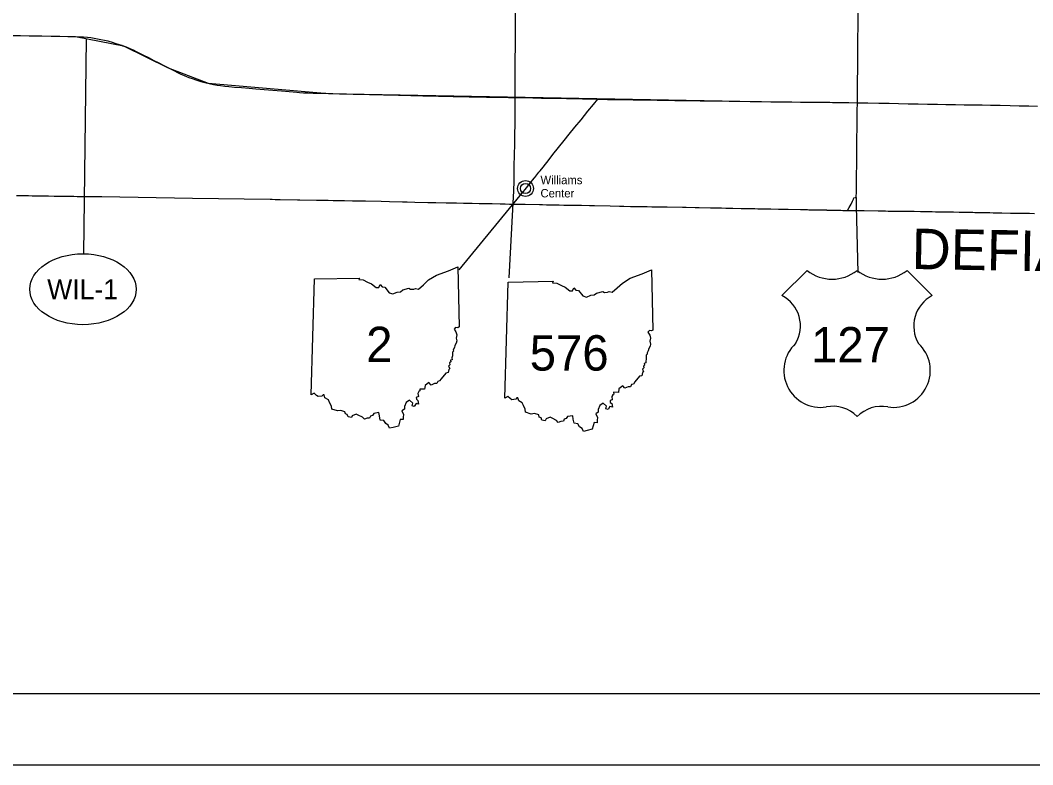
# Model space of a CAD drawing. Extents: x -66 to 795, y 0 to 440.
# Drawn here: x 240.8 to 383.6, y 0 to 105 of the extents above; entities that cross this region are included whole.
import ezdxf

# ---------------------------------------------------------------- set-up
doc = ezdxf.new("R2010")
doc.units = 0
for name, color, linetype in [('DV_X_Corp_Line', 7, 'Continuous'), ('GM_X_Adjacent_County_Text', 7, 'Continuous'), ('GM_X_County', 7, 'Continuous'), ('GM_X_State_Route', 7, 'Continuous'), ('GM_X_US_Route', 7, 'Continuous'), ('PV_P_Text', 7, 'Continuous'), ('RD_P_Fence', 7, 'Continuous'), ('SH_Border', 7, 'Continuous'), ('SH_Cut_Line', 7, 'Continuous'), ('SH_Data', 7, 'Continuous')]:
    doc.layers.add(name, color=color, linetype=linetype)

msp = doc.modelspace()

# ---------------------------------------------------------------- linework, layer by layer
at = {"layer": 'DV_X_Corp_Line'}
for radius in [1.12, 0.71]:
    msp.add_circle((312.08, 81.27), radius, dxfattribs=at)
at = {"layer": 'GM_X_County'}
msp.add_lwpolyline([(240.33, 80.3), (241.04, 80.29), (242.03, 80.26), (242.53, 80.25), (243.51, 80.24), (244.82, 80.22), (245.64, 80.21), (246.9, 80.19), (247.4, 80.19), (247.99, 80.18), (248.41, 80.17), (248.86, 80.16), (249.37, 80.16), (252.25, 80.12), (252.27, 80.12), (252.3, 80.12), (252.35, 80.12), (265.13, 79.9), (276.07, 79.77), (276.35, 79.75), (276.78, 79.74), (277.51, 79.73), (279.93, 79.69), (280.29, 79.68), (282.64, 79.64), (284.24, 79.61), (284.99, 79.59), (286.55, 79.57), (287.69, 79.55), (288.6, 79.53), (289.52, 79.51), (291.73, 79.46), (292.92, 79.44), (294.74, 79.39), (295.1, 79.39), (295.24, 79.38), (295.35, 79.38), (295.41, 79.38), (296.49, 79.35), (298.32, 79.31), (299.43, 79.28), (300.88, 79.25), (302.36, 79.23), (303.35, 79.21), (304.55, 79.18), (305.56, 79.17), (306.83, 79.14), (307.37, 79.13), (308.51, 79.11), (309.22, 79.1), (309.85, 79.08), (310.35, 79.07), (310.84, 79.06), (311.28, 79.05), (311.78, 79.05), (312.02, 79.05), (314.07, 79), (314.46, 79), (315.05, 78.98), (316.85, 78.95), (317.48, 78.94), (319.31, 78.91), (319.96, 78.9), (321.13, 78.87), (321.8, 78.86), (324.03, 78.81), (325.36, 78.78), (325.93, 78.77), (326.91, 78.75), (327.66, 78.74), (328.3, 78.73), (329.24, 78.71), (329.89, 78.7), (331.41, 78.68), (332.04, 78.67), (334.23, 78.63), (334.73, 78.63), (336.02, 78.6), (336.58, 78.59), (338.15, 78.56), (338.88, 78.54), (339.72, 78.53), (340.32, 78.51), (340.4, 78.51), (340.58, 78.51), (341.3, 78.49), (342.48, 78.47), (343.11, 78.45), (343.73, 78.44), (343.99, 78.44), (344.44, 78.43), (344.86, 78.42), (345.4, 78.41), (345.76, 78.4), (346.16, 78.39), (346.46, 78.38), (346.69, 78.38), (347.76, 78.36), (348.23, 78.35), (348.47, 78.34), (349.12, 78.33), (350.86, 78.29), (351.25, 78.29), (351.4, 78.29), (351.64, 78.29), (351.83, 78.29), (352.04, 78.28), (352.33, 78.28), (352.56, 78.27), (352.87, 78.26), (353.39, 78.25), (353.81, 78.24), (354.2, 78.24), (354.51, 78.24), (354.58, 78.23), (354.86, 78.23), (354.92, 78.23), (355.11, 78.22), (355.34, 78.21), (355.59, 78.21), (355.97, 78.2), (356.27, 78.19), (356.56, 78.19), (356.85, 78.18), (357.09, 78.18), (357.47, 78.17), (357.91, 78.17), (358.27, 78.16), (358.58, 78.16), (358.72, 78.16), (359.13, 78.16), (359.82, 78.15), (361.82, 78.11), (362.51, 78.1), (362.86, 78.1), (363.21, 78.09), (363.51, 78.09), (363.89, 78.08), (364.6, 78.07), (365.53, 78.07), (366.14, 78.05), (366.9, 78.05), (367.79, 78.04), (368.48, 78.03), (369.42, 78.01), (369.88, 78), (369.99, 78), (370.71, 77.99), (371.11, 77.98), (371.44, 77.98), (372.41, 77.96), (373.22, 77.95), (373.91, 77.93), (374.91, 77.91), (375.15, 77.91), (375.44, 77.9), (375.81, 77.9), (376.3, 77.89), (376.67, 77.88), (377.15, 77.87), (377.56, 77.86), (378.02, 77.85), (378.46, 77.85), (379.26, 77.84), (380.48, 77.81), (381.17, 77.8), (381.8, 77.79), (382.4, 77.78), (383.13, 77.77), (383.85, 77.76)], dxfattribs=at)
at = {"layer": 'GM_X_State_Route'}
for points in [[(309.8, 68.69), (310.45, 80.94), (310.47, 82.32), (310.48, 82.56), (310.48, 82.85), (310.5, 83.32), (310.5, 83.77), (310.51, 84.41), (310.54, 86.01), (310.57, 87.51), (310.59, 88.93), (310.61, 90.28), (310.62, 91.57), (310.62, 92.89), (310.64, 94.09), (310.64, 95.83), (310.65, 97.86), (310.65, 99.54), (310.67, 101.22), (310.67, 102.96), (310.68, 104.82), (310.69, 106.4)], [(302.71, 69.79), (311.33, 80.26), (312.02, 81.13), (312.04, 81.15), (312.22, 81.37), (312.69, 81.96), (313.3, 82.72), (313.33, 82.76), (313.38, 82.82), (313.96, 83.55), (314.13, 83.75), (314.56, 84.29), (315.4, 85.36), (316.09, 86.24), (316.38, 86.6), (316.72, 87.04), (317.54, 88.03), (318.26, 88.92), (319.06, 89.9), (319.93, 90.97), (320.89, 92.16), (321.68, 93.12), (322.28, 93.87)], [(358.72, 80), (358.71, 79.48), (358.7, 78.76), (358.92, 69.44)]]:
    msp.add_lwpolyline(points, dxfattribs=at)
at = {"layer": 'GM_X_US_Route'}
for points in [[(358.96, 102.97), (358.97, 103.54), (358.99, 105.1), (358.99, 106.44), (359, 107.65), (359.01, 107.92)], [(239.46, 102.86), (240.87, 102.83), (242.28, 102.81), (243.87, 102.78), (245.21, 102.76), (246.42, 102.74), (247.55, 102.71), (248.59, 102.7), (249.17, 102.67), (249.79, 102.64), (250.34, 102.6), (250.78, 102.54), (251.27, 102.47), (251.76, 102.39), (252.23, 102.29), (252.75, 102.18), (253.19, 102.08), (253.79, 101.92), (254.34, 101.74), (254.81, 101.58), (255.16, 101.46), (255.32, 101.41), (255.78, 101.24), (256.28, 101.03), (256.76, 100.81), (257.29, 100.55), (258.13, 100.13), (258.93, 99.72), (259.69, 99.34), (260.37, 98.99), (261.11, 98.6), (261.77, 98.27), (262.49, 97.89), (263.01, 97.63), (263.48, 97.41), (263.95, 97.2), (264.39, 97.03), (264.76, 96.89), (265.08, 96.78), (265.76, 96.55), (266.32, 96.37), (266.86, 96.23), (267.47, 96.08), (268.08, 95.94), (268.6, 95.84), (269.06, 95.78), (269.71, 95.69), (270.28, 95.65), (271.06, 95.57), (272.06, 95.49), (273.14, 95.4), (274.08, 95.33), (275.22, 95.22), (276.48, 95.13), (277.7, 95.03), (278.78, 94.94), (279.85, 94.85), (280.24, 94.82), (280.78, 94.78), (281.46, 94.74), (282.16, 94.72), (283.1, 94.71), (283.94, 94.69), (284.9, 94.66), (285.87, 94.64), (286.84, 94.62), (287.8, 94.59), (288.91, 94.58), (290.09, 94.54), (291.2, 94.52), (292.05, 94.5), (293.09, 94.47), (294.16, 94.45), (295.12, 94.42), (295.39, 94.41), (295.94, 94.4), (296.58, 94.38), (297.61, 94.36), (298.78, 94.34), (299.81, 94.31), (300.79, 94.28), (301.88, 94.26), (303, 94.24), (304.12, 94.21), (305.39, 94.19), (306.57, 94.17), (307.7, 94.15), (308.71, 94.13), (309.71, 94.11), (310.64, 94.09)], [(358.95, 101.77), (358.95, 102.53), (358.96, 102.87), (358.96, 102.97)], [(358.88, 93.36), (358.89, 94.87), (358.91, 96.51), (358.92, 98.05), (358.94, 99.65), (358.95, 101.12), (358.95, 101.68), (358.95, 101.77)], [(310.64, 94.09), (311.83, 94.08), (313.1, 94.05), (314.34, 94.03), (315.51, 94.01), (316.68, 93.99), (317.85, 93.97), (318.98, 93.94), (320.1, 93.93), (321.21, 93.9), (321.23, 93.9)], [(321.23, 93.9), (322.28, 93.87)], [(322.28, 93.87), (323.11, 93.85)], [(323.11, 93.85), (323.49, 93.85), (323.66, 93.84)], [(323.66, 93.84), (323.67, 93.84), (324.81, 93.82), (325.6, 93.81), (325.86, 93.81), (327.27, 93.79)], [(327.27, 93.79), (327.64, 93.78), (329.14, 93.76), (330.65, 93.74), (331.82, 93.72), (333.14, 93.7), (334.35, 93.68), (335.59, 93.67), (336.71, 93.65), (338.15, 93.63), (339.51, 93.61), (340.78, 93.59), (342.26, 93.57), (343.76, 93.55), (345.38, 93.52), (346.67, 93.5), (348.13, 93.49), (349.62, 93.47), (350.86, 93.46), (352.43, 93.45), (353.67, 93.44), (354.89, 93.42), (355, 93.42), (356.04, 93.41), (357.65, 93.38), (358.88, 93.36)], [(358.75, 81.97), (358.76, 83.26), (358.78, 84.57), (358.79, 85.84), (358.82, 87.23), (358.82, 88.4), (358.84, 89.73), (358.85, 90.96), (358.86, 92.24), (358.88, 93.36)], [(358.88, 93.36), (358.88, 93.36), (359.78, 93.34)], [(359.78, 93.34), (360.35, 93.33), (361.9, 93.31)], [(361.9, 93.31), (361.9, 93.31), (361.91, 93.31), (363.36, 93.28), (364.69, 93.25), (366.04, 93.23), (367.46, 93.2), (368.78, 93.17), (370.04, 93.15), (370.19, 93.14), (371.36, 93.12), (372.71, 93.1), (373.91, 93.08), (375.21, 93.06), (376.46, 93.05), (377.63, 93.03), (379, 93), (380.42, 92.96), (381.69, 92.94), (383.03, 92.91), (384.28, 92.89)], [(358.73, 80.94), (358.74, 81.87), (358.75, 81.97), (358.75, 81.97)], [(357.47, 78.17), (357.72, 78.61), (358, 79.08), (358.19, 79.47), (358.33, 79.75), (358.4, 79.94)], [(358.4, 79.94), (358.4, 79.94), (358.55, 79.98), (358.72, 80)], [(358.72, 80), (358.73, 80.84), (358.73, 80.94)]]:
    msp.add_lwpolyline(points, dxfattribs=at)
at = {"layer": 'PV_P_Text'}
for p, q in [((351.79, 69.7), (348.24, 66.16)), ((351.79, 69.7), (348.24, 66.16)), ((369.43, 66.16), (365.88, 69.7)), ((369.43, 66.16), (365.88, 69.7)), ((281.87, 52.15), (282.33, 68.52)), ((281.87, 52.15), (282.33, 68.52)), ((309.19, 51.7), (309.65, 68.07)), ((309.19, 51.7), (309.65, 68.07))]:
    msp.add_line(p, q, dxfattribs=at)
for points in [[(282.33, 68.52), (288.68, 68.63), (288.58, 68.43), (289.18, 68.39), (289.82, 68.04), (290.36, 67.82), (291.01, 67.3), (291.41, 67.3), (291.58, 67.73), (291.88, 67.4), (292.24, 67.34), (292.85, 66.56), (293.37, 66.39), (293.98, 66.65), (294.44, 66.7), (294.77, 66.96), (295.64, 67.19), (295.89, 67.06), (296.35, 67.08), (296.58, 67.18), (296.98, 67.09), (297.69, 67.69), (298.42, 68.39), (299.54, 69.05), (301.22, 69.68), (302.54, 70.24), (302.73, 61.74)], [(282.33, 68.52), (288.68, 68.63), (288.58, 68.43), (289.18, 68.39), (289.82, 68.04), (290.36, 67.82), (291.01, 67.3), (291.41, 67.3), (291.58, 67.73), (291.88, 67.4), (292.24, 67.34), (292.85, 66.56), (293.37, 66.39), (293.98, 66.65), (294.44, 66.7), (294.77, 66.96), (295.64, 67.19), (295.89, 67.06), (296.35, 67.08), (296.58, 67.18), (296.98, 67.09), (297.69, 67.69), (298.42, 68.39), (299.54, 69.05), (301.22, 69.68), (302.54, 70.24), (302.73, 61.74)], [(309.65, 68.07), (316, 68.18), (315.9, 67.98), (316.5, 67.94), (317.14, 67.59), (317.68, 67.37), (318.34, 66.85), (318.73, 66.85), (318.9, 67.28), (319.2, 66.95), (319.56, 66.89), (320.18, 66.11), (320.69, 65.94), (321.3, 66.21), (321.76, 66.25), (322.09, 66.52), (322.97, 66.74), (323.21, 66.61), (323.67, 66.64), (323.9, 66.74), (324.31, 66.65), (325.01, 67.24), (325.74, 67.94), (326.86, 68.61), (328.54, 69.23), (329.87, 69.8), (330.06, 61.3)], [(309.65, 68.07), (316, 68.18), (315.9, 67.98), (316.5, 67.94), (317.14, 67.59), (317.68, 67.37), (318.34, 66.85), (318.73, 66.85), (318.9, 67.28), (319.2, 66.95), (319.56, 66.89), (320.18, 66.11), (320.69, 65.94), (321.3, 66.21), (321.76, 66.25), (322.09, 66.52), (322.97, 66.74), (323.21, 66.61), (323.67, 66.64), (323.9, 66.74), (324.31, 66.65), (325.01, 67.24), (325.74, 67.94), (326.86, 68.61), (328.54, 69.23), (329.87, 69.8), (330.06, 61.3)], [(302.73, 61.74), (302.54, 61.63), (302.23, 61.68), (302.03, 61.44), (302.28, 61.05), (302.4, 60.63), (302.3, 60.16), (302.4, 59.78), (302.33, 59.46), (302.14, 59.14), (302.07, 58.84), (301.91, 58.52), (301.92, 58.34), (301.77, 58.2), (301.8, 57.67), (301.72, 57.37), (301.74, 57.12), (301.49, 57.05), (301.55, 56.84), (301.39, 56.68), (301.42, 56.4), (301.24, 56.22), (301.42, 55.87), (301.28, 55.75), (301.16, 55.32), (300.84, 55.23), (300.19, 54.44), (299.96, 54.14), (299.71, 54.07), (299.57, 53.76), (299.25, 53.76), (298.77, 53.54), (298.47, 53.91), (297.93, 53.47), (297.86, 52.96), (297.18, 52.97), (297.21, 52.72), (297.05, 52.64), (296.91, 52.38), (297, 51.92), (296.68, 51.81), (296.71, 51.54), (296.92, 51.38), (297.01, 50.87), (296.67, 50.97), (296.39, 50.54), (296.11, 50.64), (296.2, 51), (295.72, 51.44), (295.26, 51.09), (295.02, 50.53), (295.02, 50.15), (294.67, 49.93), (294.89, 49.39), (294.85, 49.03), (294.86, 48.68), (294.43, 48.69), (294.18, 47.75)], [(302.73, 61.74), (302.54, 61.63), (302.23, 61.68), (302.03, 61.44), (302.28, 61.05), (302.4, 60.63), (302.3, 60.16), (302.4, 59.78), (302.33, 59.46), (302.14, 59.14), (302.07, 58.84), (301.91, 58.52), (301.92, 58.34), (301.77, 58.2), (301.8, 57.67), (301.72, 57.37), (301.74, 57.12), (301.49, 57.05), (301.55, 56.84), (301.39, 56.68), (301.42, 56.4), (301.24, 56.22), (301.42, 55.87), (301.28, 55.75), (301.16, 55.32), (300.84, 55.23), (300.19, 54.44), (299.96, 54.14), (299.71, 54.07), (299.57, 53.76), (299.25, 53.76), (298.77, 53.54), (298.47, 53.91), (297.93, 53.47), (297.86, 52.96), (297.18, 52.97), (297.21, 52.72), (297.05, 52.64), (296.91, 52.38), (297, 51.92), (296.68, 51.81), (296.71, 51.54), (296.92, 51.38), (297.01, 50.87), (296.67, 50.97), (296.39, 50.54), (296.11, 50.64), (296.2, 51), (295.72, 51.44), (295.26, 51.09), (295.02, 50.53), (295.02, 50.15), (294.67, 49.93), (294.89, 49.39), (294.85, 49.03), (294.86, 48.68), (294.43, 48.69), (294.18, 47.75)], [(330.06, 61.3), (329.86, 61.18), (329.56, 61.24), (329.35, 61), (329.61, 60.6), (329.73, 60.18), (329.62, 59.72), (329.72, 59.33), (329.65, 59.01), (329.46, 58.7), (329.4, 58.39), (329.23, 58.07), (329.25, 57.9), (329.09, 57.75), (329.12, 57.22), (329.04, 56.93), (329.07, 56.67), (328.82, 56.61), (328.87, 56.4), (328.71, 56.23), (328.75, 55.96), (328.57, 55.78), (328.74, 55.42), (328.6, 55.31), (328.48, 54.87), (328.16, 54.79), (327.52, 53.99), (327.29, 53.69), (327.03, 53.62), (326.89, 53.31), (326.58, 53.31), (326.1, 53.1), (325.79, 53.46), (325.25, 53.02), (325.19, 52.51), (324.5, 52.53), (324.53, 52.27), (324.38, 52.19), (324.24, 51.94), (324.32, 51.48), (324, 51.36), (324.04, 51.09), (324.24, 50.93), (324.33, 50.42), (323.99, 50.52), (323.72, 50.09), (323.43, 50.19), (323.52, 50.56), (323.04, 51), (322.58, 50.65), (322.34, 50.09), (322.34, 49.71), (322, 49.48), (322.22, 48.95), (322.18, 48.58), (322.18, 48.23), (321.76, 48.25), (321.5, 47.31)], [(330.06, 61.3), (329.86, 61.18), (329.56, 61.24), (329.35, 61), (329.61, 60.6), (329.73, 60.18), (329.62, 59.72), (329.72, 59.33), (329.65, 59.01), (329.46, 58.7), (329.4, 58.39), (329.23, 58.07), (329.25, 57.9), (329.09, 57.75), (329.12, 57.22), (329.04, 56.93), (329.07, 56.67), (328.82, 56.61), (328.87, 56.4), (328.71, 56.23), (328.75, 55.96), (328.57, 55.78), (328.74, 55.42), (328.6, 55.31), (328.48, 54.87), (328.16, 54.79), (327.52, 53.99), (327.29, 53.69), (327.03, 53.62), (326.89, 53.31), (326.58, 53.31), (326.1, 53.1), (325.79, 53.46), (325.25, 53.02), (325.19, 52.51), (324.5, 52.53), (324.53, 52.27), (324.38, 52.19), (324.24, 51.94), (324.32, 51.48), (324, 51.36), (324.04, 51.09), (324.24, 50.93), (324.33, 50.42), (323.99, 50.52), (323.72, 50.09), (323.43, 50.19), (323.52, 50.56), (323.04, 51), (322.58, 50.65), (322.34, 50.09), (322.34, 49.71), (322, 49.48), (322.22, 48.95), (322.18, 48.58), (322.18, 48.23), (321.76, 48.25), (321.5, 47.31)], [(294.18, 47.75), (293.43, 47.57), (292.92, 47.46), (292.74, 47.89), (292.37, 48.12), (292.13, 48.55), (291.6, 48.61), (291.48, 49.2), (291.42, 49.67), (290.7, 49.56), (290.5, 49.26), (290.24, 49.18), (290.09, 48.89), (289.74, 48.86), (289.37, 48.73), (289.12, 49.02), (288.51, 49.31), (288.23, 49.46), (287.65, 49.22), (287.53, 48.95), (287.07, 49.07), (286.96, 49.38), (286.69, 49.47), (286.62, 49.79), (286.03, 49.97), (285.58, 49.9), (284.77, 50.16), (284.72, 50.59), (284.45, 51.11), (284.31, 51.48), (283.8, 51.75), (283.7, 52.19), (283.54, 52.17), (283.39, 52), (282.83, 51.92), (282.6, 52.09), (282.29, 52.39), (281.87, 52.15)], [(294.18, 47.75), (293.43, 47.57), (292.92, 47.46), (292.74, 47.89), (292.37, 48.12), (292.13, 48.55), (291.6, 48.61), (291.48, 49.2), (291.42, 49.67), (290.7, 49.56), (290.5, 49.26), (290.24, 49.18), (290.09, 48.89), (289.74, 48.86), (289.37, 48.73), (289.12, 49.02), (288.51, 49.31), (288.23, 49.46), (287.65, 49.22), (287.53, 48.95), (287.07, 49.07), (286.96, 49.38), (286.69, 49.47), (286.62, 49.79), (286.03, 49.97), (285.58, 49.9), (284.77, 50.16), (284.72, 50.59), (284.45, 51.11), (284.31, 51.48), (283.8, 51.75), (283.7, 52.19), (283.54, 52.17), (283.39, 52), (282.83, 51.92), (282.6, 52.09), (282.29, 52.39), (281.87, 52.15)], [(321.5, 47.31), (320.76, 47.13), (320.24, 47.02), (320.06, 47.44), (319.69, 47.67), (319.45, 48.1), (318.93, 48.16), (318.8, 48.75), (318.74, 49.23), (318.02, 49.11), (317.82, 48.82), (317.56, 48.74), (317.42, 48.44), (317.07, 48.42), (316.69, 48.28), (316.45, 48.57), (315.83, 48.86), (315.56, 49.01), (314.98, 48.78), (314.85, 48.5), (314.4, 48.62), (314.29, 48.93), (314.01, 49.02), (313.95, 49.35), (313.35, 49.52), (312.9, 49.45), (312.1, 49.71), (312.05, 50.14), (311.78, 50.67), (311.63, 51.03), (311.13, 51.31), (311.02, 51.74), (310.86, 51.73), (310.71, 51.55), (310.15, 51.47), (309.92, 51.65), (309.61, 51.95), (309.19, 51.7)], [(321.5, 47.31), (320.76, 47.13), (320.24, 47.02), (320.06, 47.44), (319.69, 47.67), (319.45, 48.1), (318.93, 48.16), (318.8, 48.75), (318.74, 49.23), (318.02, 49.11), (317.82, 48.82), (317.56, 48.74), (317.42, 48.44), (317.07, 48.42), (316.69, 48.28), (316.45, 48.57), (315.83, 48.86), (315.56, 49.01), (314.98, 48.78), (314.85, 48.5), (314.4, 48.62), (314.29, 48.93), (314.01, 49.02), (313.95, 49.35), (313.35, 49.52), (312.9, 49.45), (312.1, 49.71), (312.05, 50.14), (311.78, 50.67), (311.63, 51.03), (311.13, 51.31), (311.02, 51.74), (310.86, 51.73), (310.71, 51.55), (310.15, 51.47), (309.92, 51.65), (309.61, 51.95), (309.19, 51.7)]]:
    msp.add_lwpolyline(points, dxfattribs=at)
for centre, radius, start, end in [((355.31, 74.18), 5.7, 231.813, 308.187), ((355.31, 74.18), 5.7, 231.813, 308.187), ((362.36, 74.18), 5.7, 231.813, 308.187), ((362.36, 74.18), 5.7, 231.813, 308.187), ((346.03, 61.88), 4.82, 329.1175, 62.6108), ((346.03, 61.88), 4.82, 329.1175, 62.6108), ((371.64, 61.88), 4.82, 117.3892, 210.8825), ((371.64, 61.88), 4.82, 117.3892, 210.8825), ((353.71, 55.6), 5.2, 133.0046, 278.7282), ((353.71, 55.6), 5.2, 133.0046, 278.7282), ((363.96, 55.6), 5.2, 261.2718, 46.9954), ((363.96, 55.6), 5.2, 261.2718, 46.9954), ((355.46, 45.91), 4.65, 43.4177, 101.8742), ((355.46, 45.91), 4.65, 43.4177, 101.8742), ((362.31, 45.6), 4.94, 79.9613, 134.7468), ((362.31, 45.6), 4.94, 79.9613, 134.7468)]:
    msp.add_arc(centre, radius, start, end, dxfattribs=at)
at = {"layer": 'RD_P_Fence'}
msp.add_lwpolyline([(220.36, 103.24), (242.1, 102.81), (248.65, 102.7), (255.39, 101.38), (261.72, 98.29), (267.34, 96.11), (284.32, 94.68), (344.85, 93.53), (358.88, 93.36)], dxfattribs=at)
at = {"layer": 'SH_Border'}
msp.add_lwpolyline([(30, 430), (670, 430), (670, 10), (30, 10)], close=True, dxfattribs=at)
at = {"layer": 'SH_Cut_Line'}
msp.add_lwpolyline([(0, 0), (680, 0), (680, 440), (0, 440)], close=True, dxfattribs=at)
at = {"layer": 'SH_Data'}
msp.add_line((249.83, 72.06), (250.21, 102.39), dxfattribs=at)
msp.add_ellipse((249.69, 67.06), major_axis=(7.5, 0), ratio=0.666667, dxfattribs=at)

# ---------------------------------------------------------------- texts
at = {"layer": 'DV_X_Corp_Line'}
for s, p in [('Williams', (314.2, 81.87)), ('Center', (314.2, 80.01))]:
    msp.add_text(s, height=1.188, rotation=0, dxfattribs=at).set_placement(p)
at = {"layer": 'GM_X_Adjacent_County_Text'}
msp.add_text('DEFIANCE COUNTY', height=5.7, rotation=359.0284, dxfattribs=at).set_placement((366.5, 69.92))
at = {"layer": 'PV_P_Text'}
for s, height, p in [('2', 4.99, (289.62, 56.78)), ('127', 4.987, (352.34, 56.74)), ('576', 4.987, (312.68, 55.59))]:
    msp.add_text(s, height=height, dxfattribs=at).set_placement(p)
at = {"layer": 'SH_Data'}
msp.add_text('WIL-1', height=2.8, dxfattribs=at).set_placement((244.65, 65.66))

doc.saveas('drawing.dxf')
